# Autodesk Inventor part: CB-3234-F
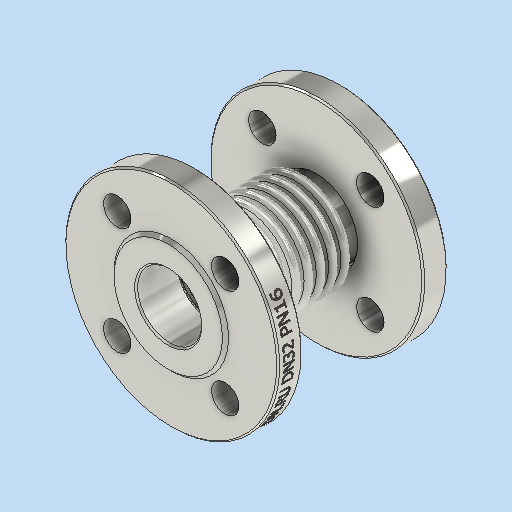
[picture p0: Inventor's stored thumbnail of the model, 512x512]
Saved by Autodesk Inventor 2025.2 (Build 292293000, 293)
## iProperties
Company: DN.RU
Created: 2026-04
Part Number: CB-3234-F
Material: Типовые
Document SubType Name: Modeling
Designer: DN.RU
Density: 8.04308 g/cm^3
Appearance: По умолчанию
Description: D140-02111
Mass: 3700 g
Surface Area: 1453.62 cm^2
Volume: 460.023 cm^3
Author: DN.RU
Title: Компенсатор сильфонный осевой DN.ru Ду32 Ру16
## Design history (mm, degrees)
sketch "Эскиз1"
  geometry: L1 (0, 0)-(0, -57.5); L2 (25, -57.5)-(25, 0); L3 (25, 0)-(0, 0); L4 (25, 0)-(25, -4); L5 (20, -4)-(30, -4); L6 (20, -6.5)-(30, -6.5); L7 (30, -1.5)-(20, -1.5); L8 (30, -5.5)-(20, -5.5); L9 (20, -2.5)-(30, -2.5); L10 (30, -9.5)-(20, -9.5); L11 (20, -10.5)-(30, -10.5); L12 (20, -12)-(30, -12); L13 (20, -14.5)-(30, -14.5); L14 (30, -13.5)-(20, -13.5); L15 (30, -17.5)-(20, -17.5); L16 (20, -18.5)-(30, -18.5); L17 (20, -20)-(30, -20); L18 (20, -22.5)-(30, -22.5); L19 (30, -21.5)-(20, -21.5); L20 (30, -25.5)-(20, -25.5); L21 (20, -26.5)-(30, -26.5); L22 (20, -28)-(30, -28); L23 (20, -30.5)-(30, -30.5); L24 (30, -29.5)-(20, -29.5); L25 (0, -57.5)-(25, -57.5); L26 (25, -57.5)-(21, -57.5); L27 (25, -25.5)-(24, -25.5); L28 (21, -57.5)-(21, -29.5); L29 (25, -26.5)-(24, -26.5); L30 (24, -26.5)-(24, -21.5); L31 (25, -18.5)-(24, -18.5); L32 (24, -18.5)-(24, -13.5); L33 (25, -10.5)-(24, -10.5); L34 (24, -10.5)-(24, -5.5); L35 (25, -2.5)-(24, -2.5); L36 (24, -2.5)-(24, 0); L37 (0, -57.5)-(0, -39.5); L38 (0, -39.5)-(70, -39.5); L39 (70, -39.5)-(70, -57.5); L40 (70, -57.5)-(0, -57.5); L41 (25, -39.5)-(25, -49.5); L42 (25, -49.5)-(27, -49.5); L43 (27, -49.5)-(27, -39.5); L44 (27, -39.5)-(25, -39.5); A1 r 2.5 centre (20, -4) between (20, -1.5) and (20, -6.5); A2 r 2.5 centre (30, -4) between (30, -6.5) and (30, -1.5); A3 r 1.5 centre (20, -4) between (20, -2.5) and (20, -5.5); A4 r 1.5 centre (30, -4) between (30, -5.5) and (30, -2.5); A5 r 1.5 centre (20, -12) between (20, -10.5) and (20, -13.5); A6 r 2.5 centre (20, -12) between (20, -9.5) and (20, -14.5); A7 r 1.5 centre (30, -12) between (30, -13.5) and (30, -10.5); A8 r 2.5 centre (30, -12) between (30, -14.5) and (30, -9.5); A9 r 1.5 centre (20, -20) between (20, -18.5) and (20, -21.5); A10 r 2.5 centre (20, -20) between (20, -17.5) and (20, -22.5); A11 r 1.5 centre (30, -20) between (30, -21.5) and (30, -18.5); A12 r 2.5 centre (30, -20) between (30, -22.5) and (30, -17.5); A13 r 1.5 centre (20, -28) between (20, -26.5) and (20, -29.5); A14 r 2.5 centre (20, -28) between (20, -25.5) and (20, -30.5); A15 r 1.5 centre (30, -28) between (30, -29.5) and (30, -26.5); A16 r 2.5 centre (30, -28) between (30, -30.5) and (30, -25.5); 20 further points
  constraints: 96 end point, 32 point on circle, 19 point on line, 16 centre point, 7 parallel, 7 perpendicular, 6 midpoint, 4 tangent, 2 vertical, 1 horizontal, 69 other
  dimensions: "d0" = 57.5 distance of L1.start L1.end; "d3" = 4 distance of L2.end L4.end; "d4" = 5 distance of L4.end L5.end; "d5" = 5 diameter of A2; "d6" = 1 distance between parallel lines of L6 L8; "d9" = 8 distance of L4.end point (25, -12); "d15" = 1 distance of L27.start L27.end; "d16" = 1 distance of L29.start L29.end; "d17" = 1 distance of L31.start L31.end; "d18" = 1 distance of L33.start L33.end; "d19" = 1 distance of L35.start L35.end; "d27" = 21 distance between parallel lines of L1 L28; "d28" = 4 distance between parallel lines of L2 L28; "d29" = 18 distance of L1.end L37.end; "d30" = 70 distance of L37.end L38.end; "d31" = 10 distance of L41.start L41.end; "d32" = 2 distance of L42.end L41.end
revolve "Вращение1" sketch "Эскиз1" stored, may be unused: angle "d20" = 360 deg
sketch "Эскиз3" dims "d33" = 100
  geometry: L1 (0, 0)-(54.414, 54.414); L2 (0, 0)-(76.954, 0); C1 r 9 at (35.355, 35.355); C2 r 9 at (-35.355, 35.355); C3 r 9 at (-35.355, -35.355); C4 r 9 at (35.355, -35.355); C5 r 21 at (0, 0) reference; C6 r 37.5 at (0, 0); C7 r 70 at (0, 0) reference; 1 further point
  constraints: 5 centre point, 4 end point, 2 coincident, 1 equal length, 1 horizontal, 1 point on line, 12 other
  dimensions: "d34" = 45 deg angle of L2 L1; "d35" = 18 diameter of C1; "d38" = 360 deg dimension on point (0, 0) C1.centre (derived); "d40" = 75 diameter of C6
  node "Эскиз — круговой массив1" dims "d38" = 360 deg (derived)
extrude "Выдавливание1" cut sketch "Эскиз3" stored distance "d41" = 10; taper "d42" = 0 deg
extrude "Выдавливание2" cut sketch "Эскиз3" distance "d43" = 2; taper "d44" = 0 deg
chamfer "Фаска2" distance "d45" = 2; stored, may be unused: second distance "d46" = 2, angle "d47" = 45 deg
chamfer "Фаска3" distance "d48" = 1; stored, may be unused: second distance "d49" = 2, angle "d50" = 45 deg
mirror "Зеркальное отражение2"
fillet "Сопряжение2" dims "d51" = 1
node "РабПлоскость2"
sketch "Эскиз4"
  geometry: L1 (-44.383, 3.589)-(46.395, 3.589); L2 (46.395, 3.589)-(46.395, 0.413); L3 (46.395, 0.413)-(-44.383, 0.413); L4 (-44.383, 0.413)-(-44.383, 3.589); 1 further point
  constraints: 2 other
feature "Рельеф2" sketch "Эскиз4" dims "d52" = 0.1, "d53" = 0
node "Твердое тело1"
node "Эскиз — прямоугольный массив1" dims "d9" = 8, "d12" = 10
